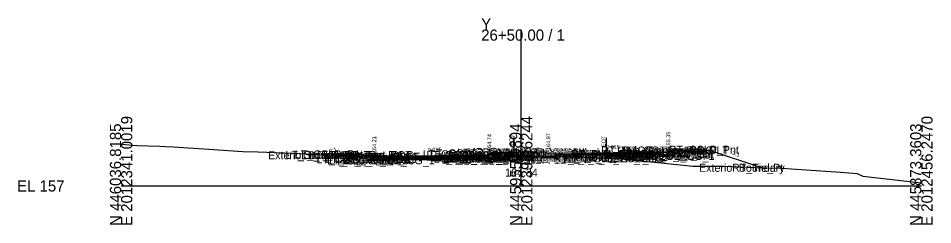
# Model space of a CAD drawing. Extents: x -26 to 3203, y -10 to 9532.
# Drawn here: x 1974.3 to 2202.8, y 490.3 to 541.9 of the extents above; entities that cross this region are included whole.
import ezdxf

# ---------------------------------------------------------------- set-up
doc = ezdxf.new("R2010")
doc.units = 0
for name, color, linetype in [('Default', 7, 'Continuous'), ('Exist CMT Pavement', 7, 'Continuous'), ('Exist Cross Section Cell', 7, 'Continuous'), ('Exist XS Center Line Elevation Label', 7, 'Continuous'), ('Exist XS Ground Line', 7, 'Continuous'), ('Prop CMT Conc Surface', 7, 'Continuous'), ('Prop CMT Concrete Structures', 7, 'Continuous'), ('Prop CMT Pvmt Course 1', 7, 'Continuous'), ('Prop CMT Pvmt Course 1 CG', 7, 'Continuous'), ('Prop CMT Pvmt Course 2', 7, 'Continuous'), ('Prop CMT Pvmt Course 2 Wedge', 7, 'Continuous'), ('Prop CMT Pvmt Course 3', 7, 'Continuous'), ('Prop CMT Pvmt Course 3 Wedge', 7, 'Continuous'), ('Prop CMT Pvmt Surface', 7, 'Continuous'), ('Prop CMT Slope Grass', 7, 'Continuous'), ('Prop CMT Subgrade Earthwork', 7, 'Continuous'), ('Prop XS Hydro Elevations', 7, 'Continuous'), ('Prop XS Label Text', 7, 'Continuous'), ('Prop XS SE Text', 7, 'Continuous'), ('Prop XS Side Slope Text', 7, 'Continuous'), ('Scratch_Level_0', 7, 'Continuous')]:
    doc.layers.add(name, color=color, linetype=linetype)

msp = doc.modelspace()

# ---------------------------------------------------------------- linework, layer by layer
at = {"layer": 'Exist CMT Pavement'}
msp.add_lwpolyline([(2098.16, 507.35), (2098.57, 507.35), (2100.04, 507.34), (2100.67, 507.34), (2101.57, 507.35), (2102.49, 507.35), (2103.12, 507.35), (2106.19, 507.33), (2109.42, 507.32), (2110.2, 507.3), (2112.26, 507.26), (2113.21, 507.23), (2114.56, 507.2), (2115.29, 507.18), (2116.8, 507.13), (2118.35, 507.08), (2118.92, 507.06), (2121.19, 506.99), (2121.19, 506.99)], dxfattribs=at)
at = {"layer": 'Exist Cross Section Cell'}
for p, q in [((2100, 500), (2100, 539.1)), ((2000, 500), (2100, 500)), ((2100, 500), (2200, 500))]:
    msp.add_line(p, q, dxfattribs=at)
at = {"layer": 'Exist XS Ground Line'}
msp.add_lwpolyline([(2000, 510.4), (2003.94, 510.09), (2009.72, 509.91), (2011.12, 509.88), (2013.1, 509.8), (2021.96, 509.15), (2030.46, 508.62), (2034.19, 508.5), (2043.12, 508.16), (2046.43, 508.02), (2047.81, 507.98), (2054.18, 507.57), (2058.43, 507.52), (2067.66, 507.12), (2080.18, 506.25), (2082.01, 506.13), (2087.39, 506.58), (2091.39, 506.91), (2092.36, 506.98), (2097.25, 507.33), (2097.7, 507.34), (2098.16, 507.35), (2098.57, 507.35), (2100.04, 507.34), (2100.67, 507.34), (2101.57, 507.35), (2102.49, 507.35), (2103.12, 507.35), (2106.19, 507.33), (2109.42, 507.32), (2110.2, 507.3), (2112.26, 507.26), (2113.21, 507.23), (2114.56, 507.2), (2115.29, 507.18), (2116.8, 507.13), (2118.35, 507.08), (2118.92, 507.06), (2121.19, 506.99), (2121.75, 506.97), (2122.46, 506.94), (2123.18, 506.91), (2134.86, 505.79), (2142.92, 504.98), (2145, 504.98), (2150.75, 504.96), (2160.53, 504.52), (2165.1, 504.44), (2179.79, 503.4), (2183.96, 503.09), (2185.4, 502.45), (2200, 500.74)], dxfattribs=at)
at = {"layer": 'Prop CMT Conc Surface'}
for points in [[(2058.75, 507.8), (2053.75, 507.9)], [(2063.25, 507.21), (2063.25, 507.71), (2062.75, 507.71)], [(2091.25, 507.73), (2092, 507.74), (2092, 507.91), (2092.76, 508.16)], [(2108.75, 508), (2106.75, 507.97), (2106.75, 508.13), (2106, 508.38)], [(2134.75, 508.4), (2136.75, 508.35)], [(2136.75, 508.35), (2136.75, 508.85), (2137.25, 508.85)], [(2065.25, 507.32), (2063.25, 507.21)]]:
    msp.add_lwpolyline(points, dxfattribs=at)
at = {"layer": 'Prop CMT Concrete Structures'}
for points in [[(2053.75, 507.57), (2053.75, 507.9)], [(2053.75, 507.9), (2058.75, 507.8)], [(2058.75, 507.47), (2053.75, 507.57)], [(2058.75, 507.8), (2058.75, 507.47)], [(2065.25, 507.32), (2063.25, 507.21), (2063.25, 507.71), (2062.75, 507.71)], [(2062.75, 507.71), (2062.75, 506.7), (2065.25, 506.74)], [(2091.25, 507.73), (2092, 507.74), (2092, 507.91), (2092.76, 508.16)], [(2091.25, 507.14), (2091.25, 507.73)], [(2092.76, 508.16), (2092.76, 507.17)], [(2108.75, 508), (2106.75, 507.97), (2106.75, 508.13), (2106, 508.38)], [(2106, 508.38), (2106, 507.37)], [(2106, 507.37), (2108.75, 507.41)], [(2108.75, 507.41), (2108.75, 508)], [(2134.75, 508.4), (2136.75, 508.35), (2136.75, 508.85), (2137.25, 508.85)], [(2137.25, 508.85), (2137.25, 507.86), (2134.75, 507.82)], [(2134.75, 507.82), (2134.75, 508.4)], [(2145.75, 509.03), (2137.75, 508.87)], [(2137.75, 508.87), (2137.75, 508.54)], [(2137.75, 508.54), (2145.75, 508.7)], [(2145.75, 508.7), (2145.75, 509.03)], [(2065.25, 506.74), (2065.25, 507.32)], [(2092.76, 507.17), (2091.25, 507.14)]]:
    msp.add_lwpolyline(points, dxfattribs=at)
at = {"layer": 'Prop CMT Pvmt Course 1'}
for points in [[(2091.25, 507.73), (2065.25, 507.32)], [(2065.25, 507.07), (2091.25, 507.48)], [(2091.25, 507.48), (2091.25, 507.73)], [(2091.25, 507.48), (2091.25, 507.48), (2091.25, 507.48)], [(2108.75, 508), (2134.75, 508.4)], [(2134.75, 508.15), (2123.18, 507.97), (2108.75, 507.75)], [(2108.75, 507.75), (2108.75, 508)], [(2108.75, 507.75), (2108.75, 507.75)], [(2134.75, 508.4), (2134.75, 508.15)], [(2065.25, 507.32), (2065.25, 507.07)]]:
    msp.add_lwpolyline(points, dxfattribs=at)
at = {"layer": 'Prop CMT Pvmt Course 1 CG'}
for points in [[(2108.75, 507.41), (2105.5, 507.36), (2105.16, 507.03)], [(2108.75, 507.08), (2108.75, 507.41)], [(2134.75, 507.82), (2137.75, 507.86), (2138.08, 507.54)], [(2134.75, 507.48), (2134.75, 507.82)], [(2138.08, 507.54), (2134.75, 507.48)], [(2065.25, 506.74), (2062.25, 506.69), (2061.91, 506.36)], [(2061.91, 506.36), (2065.25, 506.41)], [(2065.25, 506.41), (2065.25, 506.74)], [(2091.25, 507.14), (2093.26, 507.17), (2093.59, 506.85)], [(2091.25, 506.81), (2091.25, 507.14)], [(2093.59, 506.85), (2091.25, 506.81)], [(2105.16, 507.03), (2108.75, 507.08)]]:
    msp.add_lwpolyline(points, dxfattribs=at)
at = {"layer": 'Prop CMT Pvmt Course 2'}
for points in [[(2091.25, 507.48), (2065.25, 507.07)], [(2091.25, 507.14), (2091.25, 507.48)], [(2108.75, 507.75), (2108.75, 507.75)], [(2121.19, 507.94), (2134.75, 508.15)], [(2121.19, 507.61), (2121.19, 507.94)], [(2134.75, 507.82), (2121.19, 507.61)], [(2134.75, 508.15), (2134.75, 507.82)], [(2065.25, 506.74), (2091.25, 507.14)], [(2065.25, 507.07), (2065.25, 506.74)]]:
    msp.add_lwpolyline(points, dxfattribs=at)
msp.add_lwpolyline([(2108.75, 507.75), (2108.75, 507.41), (2108.75, 507.41)], close=True, dxfattribs=at)
at = {"layer": 'Prop CMT Pvmt Course 2 Wedge'}
msp.add_lwpolyline([(2108.75, 507.75), (2121.19, 507.94)], dxfattribs=at)
at = {"layer": 'Prop CMT Pvmt Course 3'}
for points in [[(2108.75, 507.41), (2108.75, 507.41), (2108.75, 507.08), (2108.75, 507.08)], [(2108.75, 507.08), (2108.75, 507.41)], [(2121.19, 507.61), (2134.75, 507.82)], [(2121.19, 507.27), (2121.19, 507.61)], [(2134.75, 507.48), (2121.19, 507.27)], [(2134.75, 507.82), (2134.75, 507.48)], [(2091.25, 507.14), (2065.25, 506.74)], [(2065.25, 506.41), (2091.25, 506.81)], [(2065.25, 506.74), (2065.25, 506.41)], [(2091.25, 506.81), (2091.25, 507.14)]]:
    msp.add_lwpolyline(points, dxfattribs=at)
at = {"layer": 'Prop CMT Pvmt Course 3 Wedge'}
msp.add_lwpolyline([(2108.75, 507.41), (2121.19, 507.61)], dxfattribs=at)
at = {"layer": 'Prop CMT Pvmt Surface'}
for points in [[(2091.25, 507.73), (2065.25, 507.32)], [(2108.75, 508), (2134.75, 508.4)]]:
    msp.add_lwpolyline(points, dxfattribs=at)
at = {"layer": 'Prop CMT Slope Grass'}
for points in [[(2053.25, 507.9), (2052.56, 507.67)], [(2062.75, 507.71), (2053.25, 507.9)], [(2092.76, 508.16), (2099.38, 508.52)], [(2106, 508.38), (2099.38, 508.52)], [(2137.25, 508.85), (2146.75, 509.04)], [(2146.75, 509.04), (2160.29, 504.53)]]:
    msp.add_lwpolyline(points, dxfattribs=at)
at = {"layer": 'Prop CMT Subgrade Earthwork'}
for points in [[(2065.25, 506.41), (2061.91, 506.36), (2060.51, 507.76)], [(2095.02, 508.28), (2093.59, 506.85)], [(2103.76, 508.43), (2105.16, 507.03)], [(2121.19, 507.27), (2134.75, 507.48)], [(2134.75, 507.48), (2138.08, 507.54), (2139.44, 508.89)], [(2134.75, 507.48), (2134.75, 507.48)], [(2091.25, 506.81), (2065.25, 506.41)], [(2065.25, 506.41), (2065.25, 506.41)], [(2093.59, 506.85), (2091.25, 506.81)], [(2091.25, 506.81), (2091.25, 506.81)], [(2091.25, 506.81), (2091.25, 506.81)], [(2105.16, 507.03), (2108.75, 507.08)], [(2108.75, 507.08), (2108.74, 507.32)], [(2108.75, 507.08), (2108.75, 507.08)], [(2108.75, 507.08), (2108.75, 507.08)], [(2121.19, 507.27), (2121.2, 506.99)]]:
    msp.add_lwpolyline(points, dxfattribs=at)
at = {"layer": 'Prop XS Label Text'}
for p, q in [((2098.16, 512.35), (2098.16, 507.35)), ((2121.19, 511.99), (2121.19, 506.99))]:
    msp.add_line(p, q, dxfattribs=at)

# ---------------------------------------------------------------- texts
at = {"layer": 'Default'}
msp.add_text('-', height=0.0001, dxfattribs=at).set_placement((2000, 500))
at = {"layer": 'Exist Cross Section Cell'}
for s, p in [('Y', (2090, 539.1)), ('26+50.00 / 1', (2090, 536.3)), ('EL 157', (1974, 498.6))]:
    msp.add_text(s, height=2.8, dxfattribs=at).set_placement(p)
for s, p in [('E 2012341.0019', (2002.8, 490)), ('E 2012398.6244', (2102.8, 490)), ('E 2012456.2470', (2202.8, 490)), ('N 446036.8185', (2000, 490)), ('N 445955.0894', (2100, 490)), ('N 445873.3603', (2200, 490))]:
    msp.add_text(s, height=2.8, rotation=90, dxfattribs=at).set_placement(p)
at = {"layer": 'Exist XS Center Line Elevation Label'}
msp.add_text('164.34', height=2, dxfattribs=at).set_placement((2095.96, 502.34))
at = {"layer": 'Prop XS Hydro Elevations'}
for s, p in [('164.21', (2063.75, 508.21)), ('164.74', (2092.5, 508.74)), ('164.97', (2107.25, 508.97)), ('165.35', (2137.25, 509.35))]:
    msp.add_text(s, height=1, rotation=90, dxfattribs=at).set_placement(p)
at = {"layer": 'Prop XS Label Text'}
for p in [(2098.06, 508.37), (2121.09, 508.01)]:
    msp.add_text('E. EOT', height=1, rotation=90, dxfattribs=at).set_placement(p)
at = {"layer": 'Prop XS SE Text'}
for p in [(2121.26, 509.17), (2076.62, 508.5)]:
    msp.add_text('0.015', height=1, rotation=0.8869, dxfattribs=at).set_placement(p)
at = {"layer": 'Prop XS Side Slope Text'}
for rotation, p in [(18.4349, (2052.19, 508.13)), (341.5651, (2152.64, 507.87))]:
    msp.add_text('3:1', height=1, rotation=rotation, dxfattribs=at).set_placement(p)
at = {"layer": 'Scratch_Level_0'}
for s, p in [('RT_Sub_Trench_Out_DLT', (2119.96, 507.89)), ('RT_CG_Top_Face', (2123.96, 507.85)), ('RT_CG_Top_BOC', (2125.49, 507.85)), ('RT_CSLP_Pnt', (2136.88, 508.04)), ('Exterior Boundary', (2036.71, 506.67)), ('LT_Sub_Trench_Out_DLT', (2041.08, 506.76)), ('LT_CSLP_Pnt', (2043.42, 506.9)), ('LT_Tie_Pt', (2045, 506.67)), ('LT_CG1_Shelf_Out', (2048.8, 505.69)), ('LT_CG_Top_Face', (2050.51, 506.71)), ('LT_CG_Top_BOC', (2051.03, 506.71)), ('LT_CG_Bot_BOC', (2051.06, 505.7)), ('LT_Sub_OEOT_CG_1', (2051.47, 505.41)), ('LT_CG_Top_Gut', (2051.49, 506.21)), ('LT_Sub_OEOP', (2052.02, 505.36)), ('LT_CG_Bot_IE', (2055.16, 505.74)), ('LT_Sub_OEOT', (2055.33, 505.41)), ('LT_PV2_OEOT', (2055.42, 506.07)), ('LT_PV3_OEOT', (2055.42, 505.74)), ('LT_PV1_OEOT', (2055.99, 506.32)), ('LT_CG_Top_Face_Med', (2075.37, 506.91)), ('LT_CG_Top_Gut_Med', (2076.35, 506.74)), ('LT_CG_Top_BOC_Med', (2077.15, 507.16)), ('LT_CG_Bot_BOC_Med', (2077.19, 506.17)), ('LT_CG_Bot_IE_Med', (2077.31, 506.14)), ('LT_Sub_IEOT_CG_1', (2078.12, 505.81)), ('LT_Sub_OEEOP', (2080.46, 505.81)), ('LT_PV2_OEEOP', (2080.56, 506.48)), ('LT_PV3_OEEOP', (2080.56, 506.14)), ('LT_Sub_IEEOP', (2081.11, 505.81)), ('LT_PV2_IEEOP', (2081.2, 506.48)), ('LT_CG1_Shelf_In', (2081.43, 506.17)), ('LT_Sub_PGL', (2082.37, 505.81)), ('LT_PV2_PGL', (2082.46, 506.48)), ('LT_PV1_PGL', (2083.03, 506.73)), ('LT_Sub_DLT_In', (2083.96, 507.28)), ('LT_Sub_IEOP', (2084.34, 505.85)), ('MD_Crown Point', (2086.45, 507.52)), ('RT_CG_Top_BOC_Med', (2090.35, 507.38)), ('RT_CG_Bot BOC In', (2091.84, 506.37)), ('RT_CG_Top_BOC In', (2091.97, 507.38)), ('RT_CG_Top FOC In', (2092.61, 507.13)), ('RT_CG_Top_Gut In', (2092.64, 506.97)), ('RT_Sub_DLT_In', (2092.66, 507.43)), ('RT_CG1_Shelf_In', (2093.63, 506.36)), ('RT_CG_Bot_IE_Med', (2094.77, 506.41)), ('RT_PV_Sub_Tie_In', (2095.25, 506.32)), ('RT_Sub_IEOT_CG_1', (2095.57, 506.08)), ('RT_Sub_IEOP', (2095.87, 506.03)), ('RT_PV_IEEOP_EG', (2096.89, 506.32)), ('RT_Sub_IEEOP', (2098.56, 506.08)), ('RT_PV2_IEEOP', (2098.66, 506.75)), ('RT_PV3_IEEOP', (2098.66, 506.41)), ('RT_Sub_PGL', (2099.82, 506.08)), ('RT_PV2_PGL', (2099.92, 506.75)), ('RT_PV3_PGL', (2099.92, 506.41)), ('RT_PV1_PGL', (2100.48, 507)), ('RT_PV_Sub_Tie_Out', (2108.09, 505.91)), ('RT_PV_OEEOP_EG', (2110.68, 505.91)), ('RT_Sub_OEEOP', (2112.35, 506.3)), ('RT_PV2_OEEOP', (2112.44, 506.97)), ('RT_PV3_OEEOP', (2112.44, 506.64)), ('RT_Sub_OEOT_CG_1', (2120.92, 506.48)), ('RT_CG1_Shelf_Out', (2124.25, 506.86)), ('RT_CG_Bot_IE', (2124.62, 506.82)), ('RT_Sub_OEOT', (2124.78, 506.48)), ('RT_PV2_OEOT', (2124.88, 507.15)), ('RT_PV3_OEOT', (2124.88, 506.82)), ('RT_CG_Top_Gut', (2124.94, 507.35)), ('RT_PV1_OEOT', (2125.44, 507.4)), ('RT_CG_Bot_BOC', (2125.52, 506.86)), ('RT_Sub_OEOP', (2128.14, 506.54)), ('Exterior Boundary', (2144.43, 503.53)), ('RT_Tie_Pt', (2152.69, 503.53))]:
    msp.add_text(s, height=2, dxfattribs=at).set_placement(p)

doc.saveas('drawing.dxf')
